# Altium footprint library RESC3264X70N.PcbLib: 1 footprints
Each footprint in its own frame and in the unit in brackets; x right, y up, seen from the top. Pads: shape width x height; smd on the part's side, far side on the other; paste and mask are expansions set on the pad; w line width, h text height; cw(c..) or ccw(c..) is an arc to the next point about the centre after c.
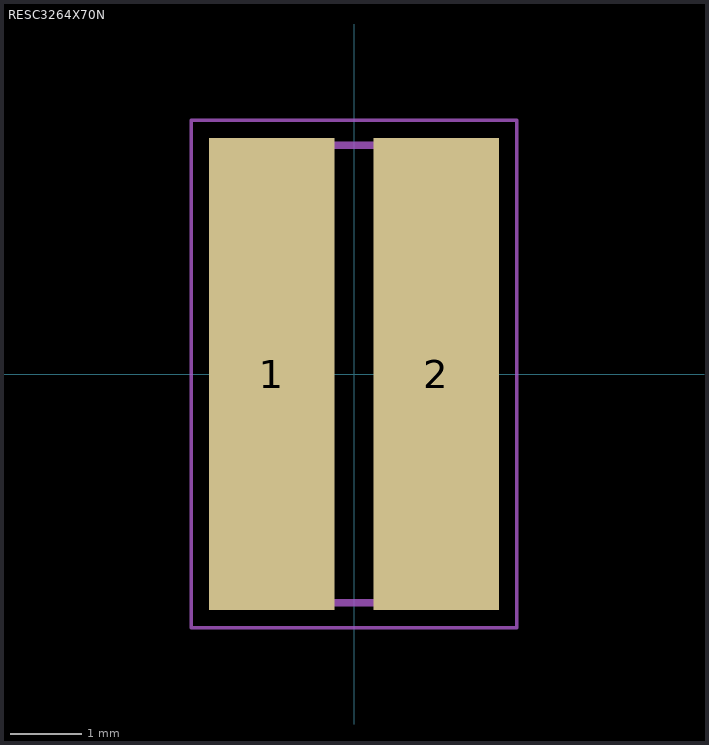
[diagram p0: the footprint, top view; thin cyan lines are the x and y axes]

## RESC3264X70N [mm]
pads (2):
  rect 1.75x6.6 smd: 1(-1.15,0) 2(1.15,0)
Mechanical 15:
  lines w0.1: -1.6,-3.2 1.6,-3.2 1.6,3.2 -1.6,3.2 -1.6,-3.2
Mechanical 20:
  lines w0.05: -2.275,-3.55 2.275,-3.55 2.275,3.55 -2.275,3.55 -2.275,-3.55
